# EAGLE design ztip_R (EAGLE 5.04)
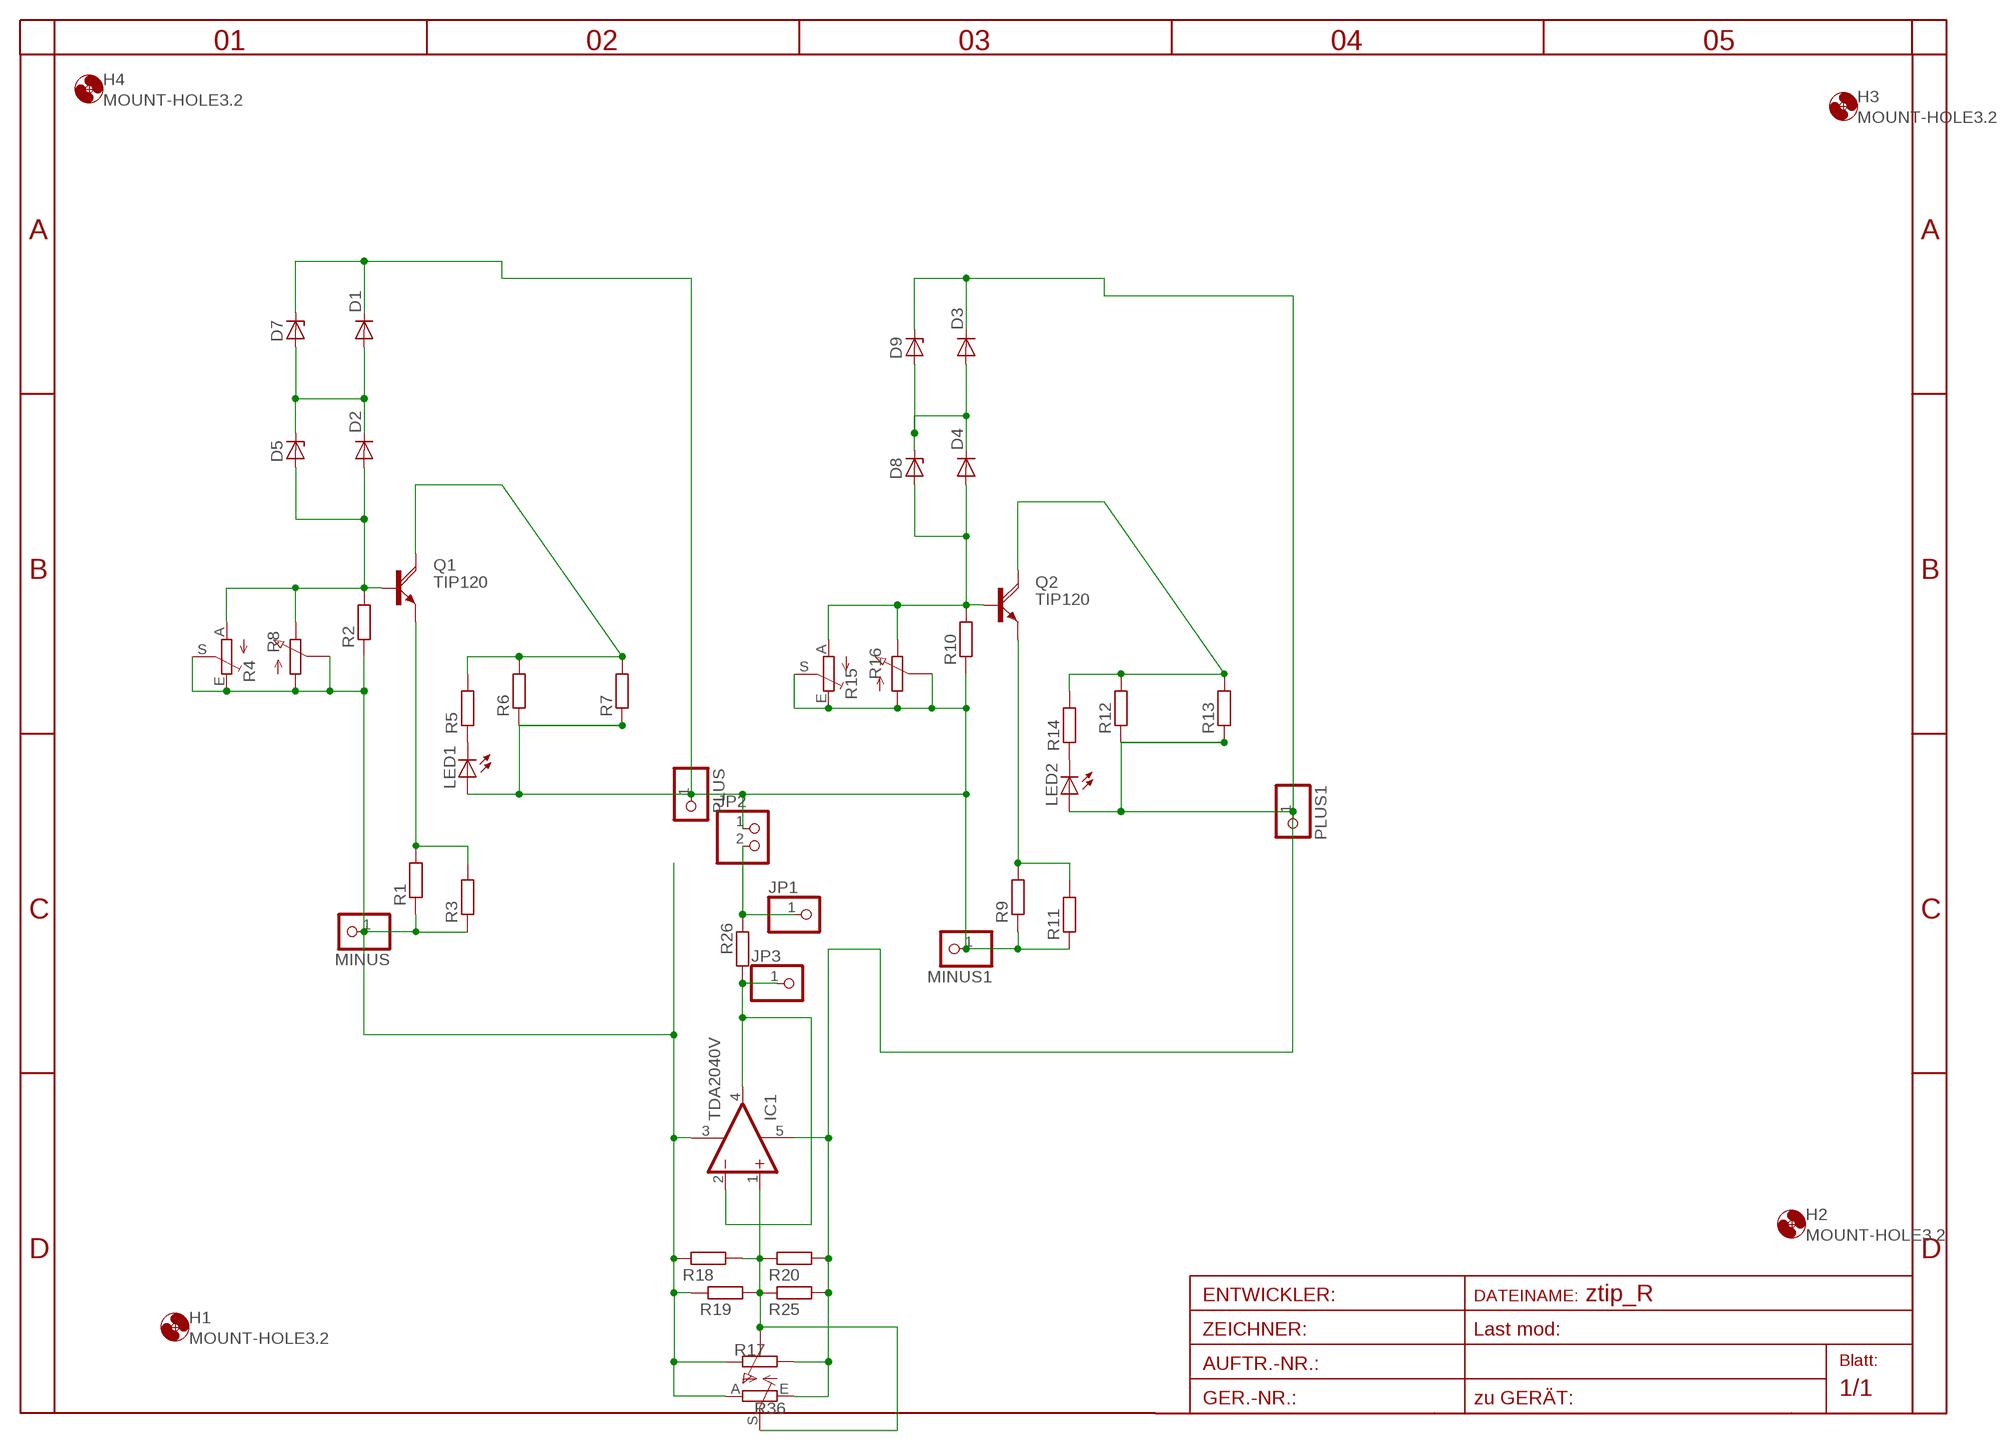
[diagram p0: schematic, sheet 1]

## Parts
D1  DIODE-MINIMELF  [MINIMELF]
D2  DIODE-MINIMELF  [MINIMELF]
D3  DIODE-MINIMELF  [MINIMELF]
D4  DIODE-MINIMELF  [MINIMELF]
D5  ZENER-DIODEZD-7.5  [ZDIO-7.5]
D7  ZENER-DIODEZD-7.5  [ZDIO-7.5]
D8  ZENER-DIODEZD-7.5  [ZDIO-7.5]
D9  ZENER-DIODEZD-7.5  [ZDIO-7.5]
H1  MOUNT-HOLE3.2  [3,2]
H2  MOUNT-HOLE3.2  [3,2]
H3  MOUNT-HOLE3.2  [3,2]
H4  MOUNT-HOLE3.2  [3,2]
IC1  TDA2040V  [CB360]
JP1  PINHD-1X1  [1X01]
JP2  PINHD-1X2  [1X02]
JP3  PINHD-1X1  [1X01]
LED1  LEDCHIP-LED0805  [CHIP-LED0805]
LED2  LEDCHIP-LED0805  [CHIP-LED0805]
MINUS  PINHD-1X1  [1X01]
MINUS1  PINHD-1X1  [1X01]
PLUS  PINHD-1X1  [1X01]
PLUS1  PINHD-1X1  [1X01]
Q1  TIP120  [TO220AH]
Q2  TIP120  [TO220AH]
R1  R-EU_R1206  [R1206]
R2  R-EU_R1206  [R1206]
R3  R-EU_R1206  [R1206]
R4  PC25  [PC25]
R5  R-EU_R1206  [R1206]
R6  R-EU_V235/17  [V235/17]
R7  R-EU_0817/22  [P0817/22]
R8  TRIM_EU-CA6V  [CA6V]
R9  R-EU_R1206  [R1206]
R10  R-EU_R1206  [R1206]
R11  R-EU_R1206  [R1206]
R12  R-EU_V235/17  [V235/17]
R13  R-EU_0817/22  [P0817/22]
R14  R-EU_R1206  [R1206]
R15  PC25  [PC25]
R16  TRIM_EU-CA6V  [CA6V]
R17  TRIM_EU-CA6V  [CA6V]
R18  R-EU_0204/7  [0204/7]
R19  R-EU_R1206  [R1206]
R20  R-EU_0204/7  [0204/7]
R25  R-EU_R1206  [R1206]
R26  R-EU_0204/5  [0204/5]
R36  PC25  [PC25]

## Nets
B: D2.A D5.A Q1.B R2.2 R4.E R8.A
B1: D4.A D8.A Q2.B R10.2 R15.E R16.A
B2: D1.C D7.C JP2.1 LED1.A MINUS1.1 PLUS.1 R6.1 R7.1 R9.1 R10.1 R11.1 R15.A R15.S R16.E R16.S
B3: D3.C D9.C IC1.5(V+) LED2.A PLUS1.1 R12.1 R13.1 R17.E R20.2 R25.2 R36.A
B-: IC1.3(V-) MINUS.1 R1.1 R2.1 R3.1 R4.A R4.S R8.E R8.S R17.A R18.1 R19.1 R36.E
C: Q1.C R5.2 R6.2 R7.2
C1: Q2.C R12.2 R13.2 R14.2
E: Q1.E R1.2 R3.2
E1: Q2.E R9.2 R11.2
INV_1: IC1.2(-IN) IC1.4(OUT) JP3.1 R26.2
N$1: JP1.1 JP2.2 R26.1
N$5: LED2.C R14.1
N$6: D3.A D4.C D8.C D9.A
N$7: D1.A D2.C D5.C D7.A
N$17: LED1.C R5.1
NON_I1: IC1.1(+IN) R17.S R18.2 R19.2 R20.1 R25.1 R36.S

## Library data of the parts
D1-D4 = diode-1:DIODE-: DIODE
D5 D7-D9 = diode-1:ZENER-DIODE: Z-Diode
H1-H4 = holes:MOUNT-HOLE: MOUNTING HOLE with drill center marker
IC1 = linear:TDA2040: Power OP AMP
JP1 JP3 MINUS MINUS1 PLUS PLUS1 = pinhead:PINHD-1X1: PIN HEADER
JP2 = pinhead:PINHD-1X2: PIN HEADER
LED1 LED2 = led:LED: LED
Q1 Q2 = transistor-power:TIP120: NPN DARLINGTON TRANSISTOR
R1-R3 R5-R7 R9-R14 R18-R20 R25 R26 = rcl-2:R-EU_: RESISTOR, European symbol
R4 R15 R36 = pot-vitrohm:PC25: VITROHM POTENTIOMETER
R8 R16 R17 = pot:TRIM_EU-: POTENTIOMETER

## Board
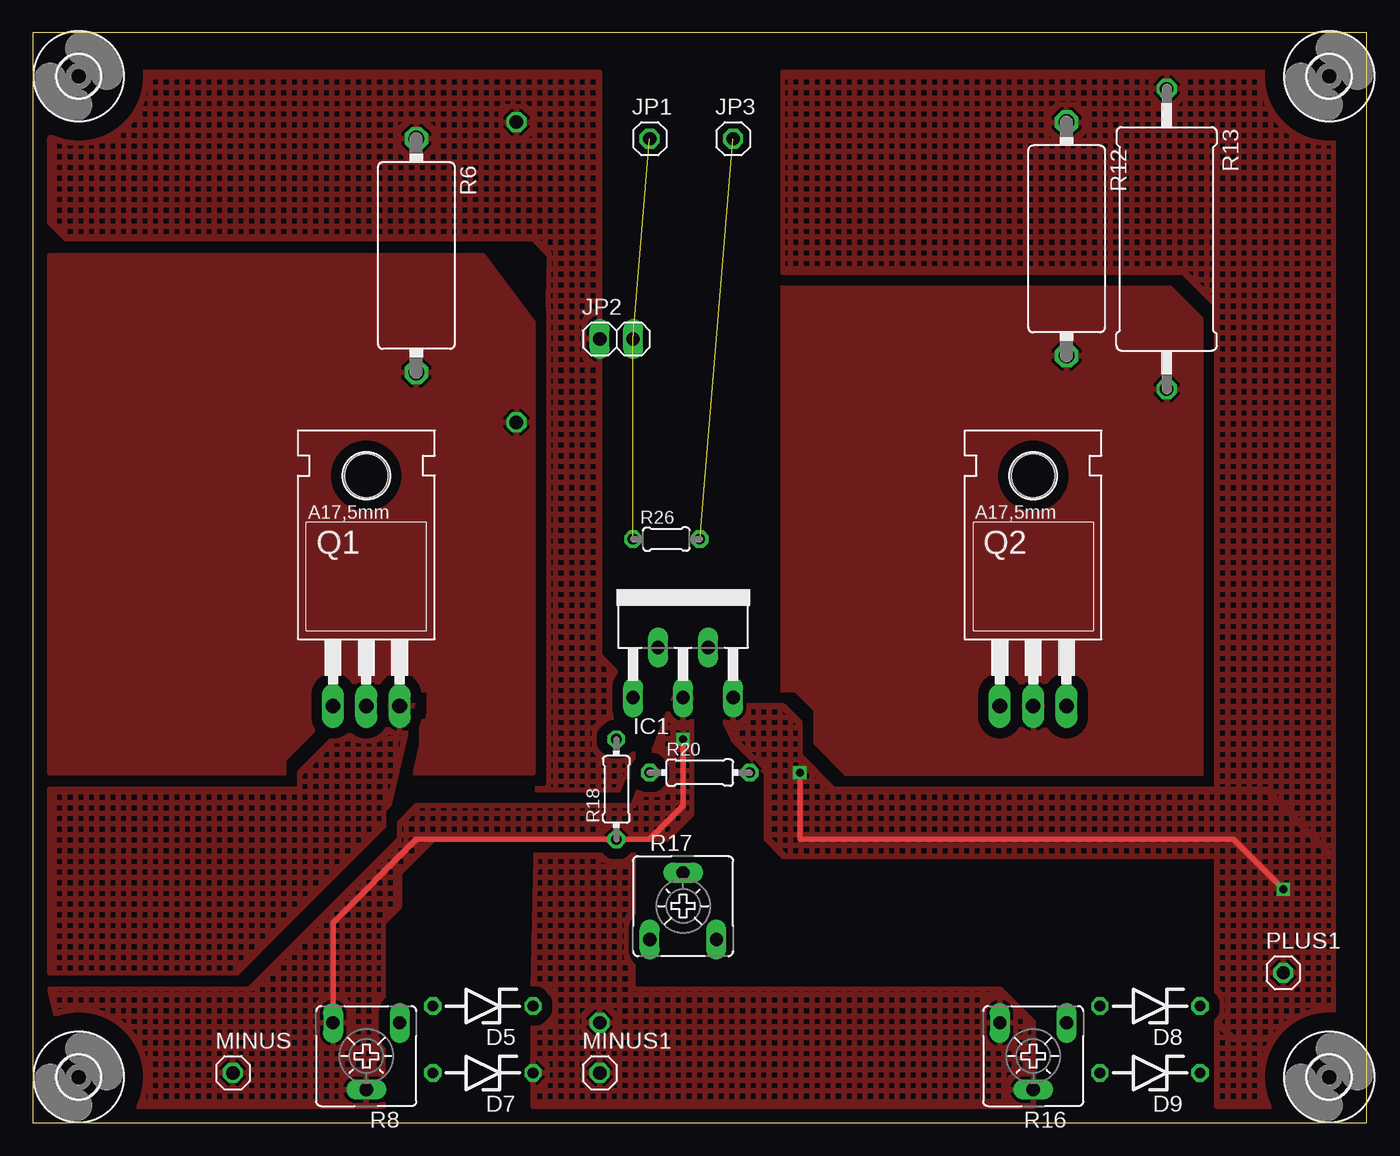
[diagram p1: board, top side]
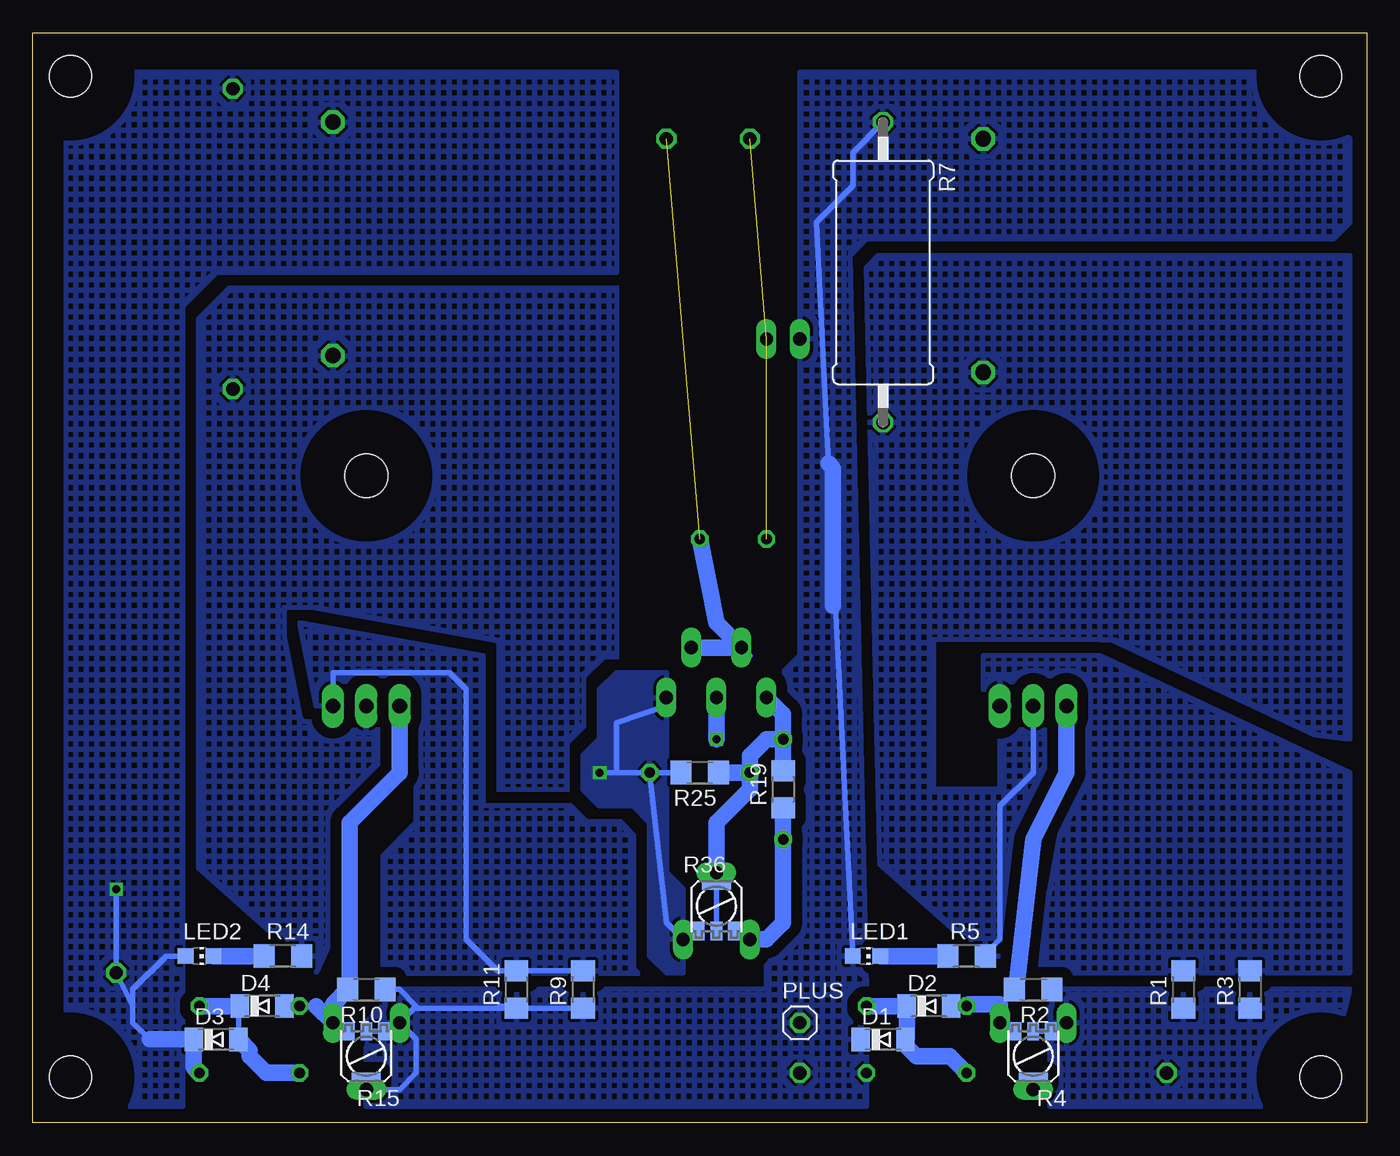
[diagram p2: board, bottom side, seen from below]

Size 101.6 x 83 mm. Coordinates in mm from the lower left corner, seen from the top.
Outline: 0,0 101.6,0 101.6,83 0,83 0,0
Copper layers (1*16): Top 0.035mm / dielectric 1.5mm / Bottom 0.035mm
Design rules "default": minimum track width 10mil, minimum drill 24mil, track to track 8mil, track to pad 8mil, pad to pad 8mil, via to via 8mil, smd to smd 8mil, copper to edge 40mil, drill to drill 8mil, minimum pad ring 10mil, minimum via ring 8mil, stop-mask expansion 4mil, vias tented up to drill 0mil, thermal gap 10mil

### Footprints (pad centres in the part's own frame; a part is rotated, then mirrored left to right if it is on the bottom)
MINIMELF = smd 1.4 x 1.8: A 1.7,0; C -1.7,0
ZDIO-7.5 = drill 0.813 octagon: A 3.81,0; C -3.81,0
3,2 = hole 3.2: 0,0
CB360 = drill 1.016 long: 1 -3.81,-8.255; 2 -1.905,-4.445; 3 0,-8.255; 4 1.905,-4.445; 5 3.81,-8.255
1X01 = drill 1.016 octagon: 1 0,0
1X02 = drill 1.016 long: 1 -1.27,0; 2 1.27,0
CHIP-LED0805 = smd 1.2 x 1.2: A 0,-1.05; C 0,1.05
TO220AH = drill 1.118 long: B -2.54,-6.35; C 0,-6.35; E 2.54,-6.35 | hole 3.302: 0,11.176
R1206 = smd 1.6 x 1.803: 1 -1.422,0; 2 1.422,0
PC25 = smd 2.2 x 0.8: 4 0,1.65 | smd 0.9 x 1.4: A -1.35,-1.9; E 1.35,-1.9; S 0,-1.9
V235/17 = drill 1.194 octagon: 1 -8.89,0; 2 8.89,0
P0817/22 = drill 1.016 octagon: 1 -11.43,0; 2 11.43,0
CA6V = drill 1.016 long: A -2.54,-2.54; E 2.54,-2.54; S 0,2.54
0204/7 = drill 0.813 octagon: 1 -3.81,0; 2 3.81,0
0204/5 = drill 0.813 octagon: 1 -2.54,0; 2 2.54,0

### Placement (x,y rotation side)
D1  36.83,6.35 0 bottom
D2  33.34,8.89 0 bottom
D3  87.63,6.35 0 bottom
D4  84.14,8.89 0 bottom
D5  34.29,8.89 180 top
D7  34.29,3.81 180 top
D8  85.09,8.89 180 top
D9  85.09,3.81 180 top
H1  3.49,79.69 0 top
H2  98.74,79.69 0 top
H3  3.49,3.49 0 top
H4  98.74,3.49 0 top
IC1  49.53,40.64 0 top
JP1  46.99,74.93 0 top
JP2  44.45,59.69 0 top
JP3  53.34,74.93 0 top
LED1  38.1,12.7 270 bottom
LED2  88.9,12.7 270 bottom
MINUS  15.24,3.81 0 top
MINUS1  43.18,3.81 0 top
PLUS  43.18,7.62 0 bottom
PLUS1  95.25,11.43 0 top
Q1  25.4,38.1 0 top
Q2  76.2,38.1 0 top
R1  13.97,10.16 90 bottom
R2  25.4,10.16 180 bottom
R3  8.89,10.16 90 bottom
R4  25.4,5.08 180 bottom
R5  30.48,12.7 0 bottom
R6  29.21,66.04 270 top
R7  36.83,64.77 270 bottom
R8  25.4,5.08 180 top
R9  59.69,10.16 90 bottom
R10  76.2,10.16 180 bottom
R11  64.77,10.16 90 bottom
R12  78.74,67.31 270 top
R13  86.36,67.31 270 top
R14  82.55,12.7 0 bottom
R15  76.2,5.08 180 bottom
R16  76.2,5.08 180 top
R17  49.53,16.51 0 top
R18  44.45,25.4 90 top
R19  44.45,25.4 90 bottom
R20  50.8,26.67 0 top
R25  50.8,26.67 180 bottom
R26  48.26,44.45 0 top
R36  49.53,16.51 0 bottom

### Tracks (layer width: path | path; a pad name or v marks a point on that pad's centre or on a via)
B
  Bottom 0.406: R4.E 27.3,6.98 R8.A | 27.94,9.04 R2.2 26.67,10.31 | 30.33,9.04 D5.A D2.A
  Bottom 1.27: R8.A 27.94,9.04 30.33,9.04 | Q1.B 22.86,26.67 25.4,21.59 26.67,10.31
B1
  Bottom 0.406: R10.2 77.47,10.16 | D4.A D8.A 80.01,8.89 | R16.A 78.19,7.62 R15.E
  Bottom 1.27: Q2.B 73.66,26.67 77.47,22.86 77.47,10.16 | 80.01,8.89 R16.A 78.74,9.04 R10.2
B2
  Bottom 0.406: LED1.A 41,50.22 41.91,68.58 39.15,71.34 39.15,73.88 R7.1 | R9.1 R11.1 | R11.1 65.89,8.74 66.04,8.89 64.92,8.89 R11.1 | R11.1 72.39,8.74 | 72.39,8.74 72.54,8.74 R16.E | R16.S 73.66,2.54 72.39,3.81 72.39,6.35 R16.E | R10.1 73.66,10.16 72.39,8.89 72.39,8.74 | R15.S R15.A 74.3,6.98 R16.E
  Bottom 1.27: 40.64,39.37 40.64,49.85 41,50.22
  pour Bottom (isolate 0.813, hatched): 38.1,10.16 38.1,1.27 76.2,1.27 76.2,7.62 73.66,10.16 45.72,10.16 45.72,33.02 43.18,35.56 43.18,80.01 5.08,80.01 1.27,74.93 1.27,68.58 2.54,67.31 38.1,67.31 39.37,66.04
  pour Top (isolate 0.813, rank 5, hatched): 38.1,10.16 38.1,1.27 76.2,1.27 76.2,7.62 73.66,10.16 45.72,10.16 45.72,33.02 43.18,35.56 43.18,80.01 3.81,80.01 1.27,74.93 1.27,68.58 2.54,67.31 38.1,67.31 39.37,66.04
B3  (via drill 0.6)
  Top 0.406: v58.42,26.67 58.42,21.59 91.44,21.59 v95.25,17.78
  Bottom 0.406: IC1.5 53.34,31.75 57.15,30.48 57.15,26.67 | R20.2 57.15,26.67 | R20.2 53.34,15.24 R17.E 51.43,14.61 R36.A | R20.2 R25.2 | 57.15,26.67 v58.42,26.67 | v95.25,17.78 PLUS1.1 93.98,8.89 | LED2.A 91.44,12.7 93.98,10.16 93.98,8.89 | 93.98,8.89 93.98,7.62 92.71,6.35
  Bottom 1.27: 92.71,6.35 D3.C 89.33,4.24 D9.C
  pour Top (isolate 0.813, hatched): 52.07,31.75 57.15,31.75 58.42,30.48 58.42,27.94 60.96,25.4 93.98,25.4 99.06,20.32 99.06,5.08 96.52,1.27 90.17,1.27 90.17,20.32 57.15,20.32 55.88,21.59 55.88,26.67 53.34,29.21
  pour Top (isolate 0.813, hatched): 57.15,80.01 97.79,80.01 99.06,76.2 99.06,7.62 97.79,6.35 91.44,6.35 90.17,7.62 90.17,62.23 87.63,64.77 57.15,64.77
  pour Bottom (isolate 0.813, hatched): 57.15,80.01 97.79,80.01 99.06,76.2 99.06,1.27 90.17,1.27 90.17,62.23 87.63,64.77 57.15,64.77
  pour Bottom (isolate 0.813): 53.34,34.29 53.34,19.05 52.07,17.78 52.07,12.7 52.07,11.43 53.34,11.43 54.61,12.7 54.61,22.86 55.88,24.13 58.42,24.13 59.69,25.4 59.69,27.94 58.42,29.21 58.42,33.02 57.15,34.29
B-  (via drill 0.6)
  Top 0.406: v49.53,29.21 49.53,24.13 46.99,21.59 | 46.99,21.59 R18.1 | 46.99,21.59 29.21,21.59 22.86,15.24 R8.E
  Bottom 0.406: R4.A R4.S | R36.E 47.63,14.61 R17.A
  Bottom 1.27: v49.53,29.21 IC1.3 | R17.A 45.72,13.97 44.45,15.24 R18.1 R19.1
  pour Bottom (isolate 0.813, rank 2, hatched): 1.27,10.16 24.13,10.16 24.13,1.27 6.35,1.27 2.54,5.08
  pour Top (isolate 0.813, rank 2, hatched): 1.27,10.16 16.51,10.16 27.94,21.59 27.94,22.86 29.21,24.13 45.72,24.13 48.9,32.38 50.16,32.38 50.16,23.5 48.26,21.59 30.48,21.59 27.94,19.05 27.94,16.51 26.67,15.24 26.67,1.27 6.35,1.27 2.54,5.08
C
  Bottom 0.406: Q1.C 25.4,26.67 27.94,24.13 27.94,13.97 29.21,12.7 R5.2
  pour Bottom (isolate 0.813, rank 3, hatched): 1.27,66.04 43.18,66.04 43.18,62.23 44.45,62.23 40.64,22.86 29.21,12.7 27.94,12.7 25.4,16.51 24.13,30.48 25.4,31.75 27.94,29.21 27.94,25.4 33.02,25.4 33.02,36.83 20.32,36.83 12.7,33.02 11.43,30.48 1.27,29.21
  pour Top (isolate 0.813, rank 4): 1.27,66.04 34.29,66.04 38.1,60.96 38.1,26.67 1.27,26.67
C1
  pour Top (isolate 0.813, rank 4): 57.15,64.77 90.17,64.77 93.98,59.69 93.98,25.4 57.15,25.4
  pour Bottom (isolate 0.813, rank 3, hatched): 57.15,64.77 93.98,64.77 93.98,60.96 95.25,60.96 91.44,21.59 80.01,11.43 73.66,25.4 57.15,25.4
E
  pour Bottom (isolate 0.813, rank 2, hatched): 1.27,26.67 20.32,35.56 29.21,35.56 29.21,33.02 27.94,31.75 21.59,31.75 24.13,17.78 26.67,12.7 25.4,11.43 1.27,11.43
  pour Top (isolate 0.813, rank 3, hatched): 1.27,25.4 20.32,25.4 20.32,26.67 26.67,33.02 29.21,33.02 24.13,11.43 1.27,11.43
E1
  Bottom 0.406: R9.2 R11.2 66.19,11.58 68.58,13.97 68.58,33.02 69.85,34.29 78.74,34.29 Q2.E
  pour Bottom (isolate 0.813, rank 2, hatched): 52.07,24.13 67.31,24.13 67.31,35.56 81.28,38.1 80.01,31.75 74.93,31.75 72.39,29.21 72.39,22.86 74.93,20.32 74.93,10.16 52.07,10.16
INV_1  (1 unrouted)
  Bottom 0.406: IC1.2 46.99,35.56
  Bottom 1.27: IC1.4 IC1.2 49.53,38.1 R26.2
N$1  (2 unrouted)
N$5
  Bottom 1.27: R14.1 LED2.C
N$6
  Bottom 0.406: 85.09,5.08 85.09,5.51 | D3.A 85.93,8.8 D4.C
  Bottom 1.27: D9.A 83.82,3.81 85.09,5.08 | 85.09,5.51 D3.A | D4.C D8.C
N$7
  Bottom 0.406: 35.04,6.44 D1.A 35.13,5.92
  Bottom 1.27: D5.C D2.C 35.04,6.44 | 35.13,5.92 34.29,5.08 31.75,5.08 D7.A
N$17
  Bottom 1.27: R5.1 LED1.C
NON_I1
  Bottom 0.406: R36.S R17.S
  Bottom 1.27: R18.2 44.45,31.11 IC1.1 | R20.1 46.99,27.94 45.72,29.21 R18.2 | R20.1 R25.1 | R18.2 R19.2 | R17.S 49.53,22.86 46.99,25.4 R20.1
